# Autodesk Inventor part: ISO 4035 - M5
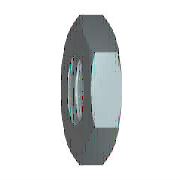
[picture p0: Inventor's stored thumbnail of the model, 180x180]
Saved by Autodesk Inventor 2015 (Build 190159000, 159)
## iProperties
Created: 2012-02
Part Number: ISO 4035 - M5
Material: Stainless Steel, 440C
Description: Hexagon thin nuts (chamfered) - Product grades A and B
Document SubType Name: Modeling
Standard: ISO 4035
Designer: 1103005
Standard Revision: Third edition 1999-08-15
Standards Organization: ISO
Language: en-US
Size Designation: M5
Categories: <MemberInstance><Categories><Category DisplayName="Fasteners" InternalName="e4da775c-781d-43d5-af7c-5136215cf5a6" Mnemonic="FSTN"><Category DisplayName="Nuts" I
Density: 7.75 g/cm^3
Appearance: Semi-Polished
IsCustomPart: 1
Author: 1103005
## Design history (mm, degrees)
sketch "Sketch1"
  geometry: L1 (-4.619, 0)-(-2.309, 4); L2 (-2.309, 4)-(2.309, 4); L3 (2.309, 4)-(4.619, 0); L4 (4.619, 0)-(2.309, -4); L5 (2.309, -4)-(-2.309, -4); L6 (-2.309, -4)-(-4.619, 0); 2 further points
  constraints: 12 end point, 1 coincident, 1 horizontal, 11 other
  dimensions: "d0" = 9.2376 distance of L3.end L1.start (= 1.1547 x SW)
extrude "Body" new body sketch "Sketch1" distance "d1" = 2.7 (= KOH); taper "d2" = 0 deg
sketch "Sketch2"
  geometry: L1 (0, 2.309)-(0, 4.619) reference; L2 (0, 4.619)-(2.7, 4.619) reference; L3 (2.7, 2.309)-(2.7, 4.619) reference; L4 (-0.54, 0)-(3.24, 0) reference; L5 (0.675, 4.619)-(0, 3.45); L6 (2.025, 4.619)-(2.7, 3.45)
  constraints: 4 end point, 4 point on line
  dimensions: "d3" = 30 deg angle of L1 L5 (= ANG1); "d4" = 30 deg angle of L3 L6 (= ANG2); "d5" = 6.9 diameter of L5.end L4 (= SW0); "d6" = 6.9 diameter of L6.end L4 (= SW01)
revolve "Chamfer1" sketch "Sketch2" stored, may be unused: angle "d7" = 90 deg
sketch "Sketch3"
  geometry: 4 further points
  constraints: 1 coincident, 1 other
hole "Thread" sketch "Sketch3" at (0, 0) diameter "d25" = 4.134; stored, may be unused: countersink angle "d29" = 82 deg, drill point angle "d31" = 118 deg; dims "d26" = 6, "d27" = 4, "d28" = 2, "d30" = 8
workaxis "Work Axis1"
workplane "Work Plane1"
body "Solid1"
chamfer "Chamfer2" distance "d8" = 0.43301 (= -0.5 x GD1 + 0.5 x NND); stored, may be unused: angle "d9" = 30 deg, second distance "d40" = 0.43301 (= -0.5 x GD1 + 0.5 x NND)
chamfer "Chamfer3" distance "d10" = 0.43301 (= -0.5 x GD1 + 0.5 x NND); stored, may be unused: angle "d11" = 30 deg, second distance "d41" = 0.43301 (= -0.5 x GD1 + 0.5 x NND)
other parameters: "ANG1" = 30 deg [user parameter; used in 1 equation term], "ANG2" = 30 deg [user parameter; used in 1 equation term], "NND" = 5 [user parameter; used in 4 equation terms], "KOH" = 2.7 [user parameter; used in 1 equation term], "SW" = 8 [user parameter; used in 2 equation terms], "SW0" = 6.9 [user parameter; used in 2 equation terms], "SW01" = 6.9 (= SW0) [user parameter; used in 1 equation term], "GD1" = 4.13397 (computed from THREADDIA, PTC, TOA) [user parameter; used in 4 equation terms], "d13" = 0, "d14" = 0, "d39" = 0, "d42" = 0, "GUL" = 0.43301 (= 0.541266 x PTC) [user parameter], "TPU" = 12.5 (computed from PTC) [user parameter], "THREADDIA" = 5 [user parameter; used in 1 equation term], "TOA" = 30 deg [user parameter; used in 1 equation term], "PTC" = 0.8 [user parameter; used in 4 equation terms], "E0" = 9.24 (= 1.155 x SW) [user parameter], "GAL" = 0.43301 (= 0.541266 x PTC) [user parameter]
